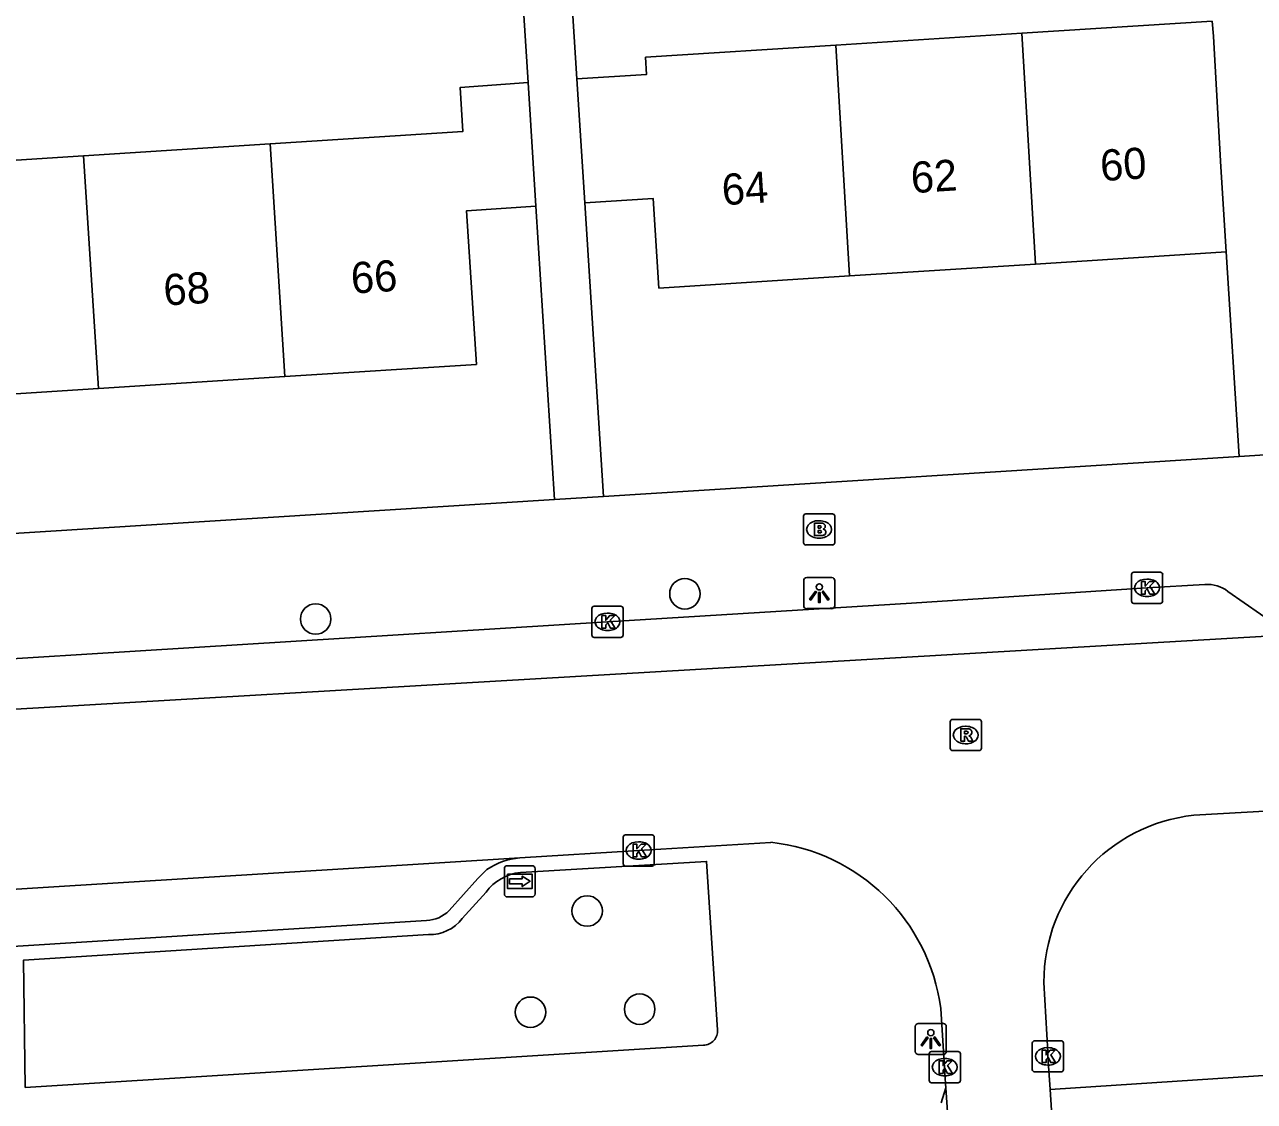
# Model space of a CAD drawing. Extents: x 159053 to 160041, y 380450 to 381422.
# Drawn here: x 159703.32 to 159742.79, y 381180.89 to 381215.45 of the extents above; entities that cross this region are included whole.
import ezdxf

# ---------------------------------------------------------------- set-up
doc = ezdxf.new("R2010")
doc.units = 0
for name, color, linetype in [('IMGEO_Boom', 7, 'Continuous'), ('IMGEO_Brandkraan', 7, 'Continuous'), ('IMGEO_Kolk', 7, 'Continuous'), ('IMGEO_Lichtpunt', 7, 'Continuous'), ('IMGEO_Pand', 7, 'Continuous'), ('IMGEO_Pand_nummerreeks', 7, 'Continuous'), ('IMGEO_Rijbaan_lokaal_open', 7, 'Continuous'), ('IMGEO_Rioolput', 7, 'Continuous'), ('IMGEO_Voetpad_open', 7, 'Continuous'), ('IMGEO_Wegwijzer', 7, 'Continuous')]:
    doc.layers.add(name, color=color, linetype=linetype)

msp = doc.modelspace()

# ---------------------------------------------------------------- linework, layer by layer
at = {"layer": 'IMGEO_Boom'}
for centre in [(159724.509, 381197.185), (159712.658, 381196.375), (159721.37, 381187.005), (159719.552, 381183.756), (159723.058, 381183.854)]:
    msp.add_circle(centre, 0.489, dxfattribs=at)
at = {"layer": 'IMGEO_Brandkraan'}
for p, q in [((159728.315, 381198.824), (159728.315, 381199.676)), ((159728.39, 381199.75), (159729.242, 381199.75)), ((159729.316, 381199.676), (159729.316, 381198.824)), ((159728.803, 381199.53), (159728.828, 381199.53)), ((159728.826, 381198.97), (159728.801, 381198.97)), ((159729.242, 381198.75), (159728.39, 381198.75))]:
    msp.add_line(p, q, dxfattribs=at)
for points in [[(159728.315, 381198.824), (159728.315, 381199.676)], [(159728.39, 381199.75), (159729.242, 381199.75)], [(159729.316, 381199.676), (159729.316, 381198.824)], [(159728.663, 381199.45), (159728.663, 381199.05), (159728.876, 381199.05)], [(159728.894, 381199.45), (159728.663, 381199.45)], [(159728.842, 381199.369), (159728.788, 381199.369), (159728.788, 381199.293)], [(159728.788, 381199.293), (159728.841, 381199.293)], [(159728.85, 381199.217), (159728.788, 381199.217), (159728.788, 381199.136)], [(159728.788, 381199.136), (159728.85, 381199.136)], [(159729.242, 381198.75), (159728.39, 381198.75)]]:
    msp.add_lwpolyline(points, dxfattribs=at)
for centre, radius, start, end in [((159728.392, 381199.674), 0.0765, 91.552, 178.448), ((159728.392, 381199.674), 0.0765, 91.552, 178.448), ((159729.24, 381199.674), 0.0765, 1.552, 88.448), ((159729.24, 381199.674), 0.0765, 1.552, 88.448), ((159728.843, 381199.331), 0.0379, 267.8285, 90.9355), ((159728.851, 381199.176), 0.0404, 269.8759, 90.5077), ((159728.898, 381199.305), 0.145, 59.4692, 91.5367), ((159728.923, 381199.352), 0.0922, 285.5137, 58.1501), ((159728.928, 381199.16), 0.105, 301.3115, 78.989), ((159728.392, 381198.826), 0.0765, 181.552, 268.448), ((159728.392, 381198.826), 0.0765, 181.552, 268.448), ((159728.882, 381199.301), 0.251, 268.6676, 293.5347), ((159729.24, 381198.826), 0.0765, 271.552, 358.448), ((159729.24, 381198.826), 0.0765, 271.552, 358.448)]:
    msp.add_arc(centre, radius, start, end, dxfattribs=at)
for centre, major_axis, ratio, start_param, end_param in [((159728.802, 381199.25), (-0.387, 0.002), 0.722429, 4.712389, 7.853982), ((159728.827, 381199.25), (-0.39, 0.002), 0.717154, 1.570796, 4.712389)]:
    msp.add_ellipse(centre, major_axis=major_axis, ratio=ratio, start_param=start_param, end_param=end_param, dxfattribs=at)
at = {"layer": 'IMGEO_Kolk'}
for p, q in [((159738.841, 381196.951), (159738.841, 381197.803)), ((159738.916, 381197.877), (159739.768, 381197.877)), ((159739.329, 381197.657), (159739.354, 381197.657)), ((159739.842, 381197.803), (159739.842, 381196.951)), ((159721.598, 381196.786), (159722.45, 381196.786)), ((159739.768, 381196.877), (159738.916, 381196.877)), ((159739.352, 381197.097), (159739.327, 381197.097)), ((159721.523, 381195.86), (159721.523, 381196.712)), ((159722.011, 381196.566), (159722.036, 381196.566)), ((159722.524, 381196.712), (159722.524, 381195.86)), ((159722.034, 381196.006), (159722.009, 381196.006)), ((159722.45, 381195.786), (159721.598, 381195.786)), ((159722.526, 381188.521), (159722.526, 381189.373)), ((159722.601, 381189.447), (159723.453, 381189.447)), ((159723.527, 381189.373), (159723.527, 381188.521)), ((159723.014, 381189.227), (159723.039, 381189.227)), ((159723.037, 381188.667), (159723.012, 381188.667)), ((159723.453, 381188.447), (159722.601, 381188.447)), ((159735.658, 381181.914), (159735.658, 381182.766)), ((159735.733, 381182.84), (159736.585, 381182.84)), ((159736.146, 381182.62), (159736.171, 381182.62)), ((159736.659, 381182.766), (159736.659, 381181.914)), ((159732.348, 381181.568), (159732.348, 381182.42)), ((159732.423, 381182.494), (159733.275, 381182.494)), ((159732.836, 381182.274), (159732.861, 381182.274)), ((159733.349, 381182.42), (159733.349, 381181.568)), ((159736.585, 381181.84), (159735.733, 381181.84)), ((159736.169, 381182.06), (159736.144, 381182.06)), ((159733.275, 381181.494), (159732.423, 381181.494)), ((159732.859, 381181.714), (159732.834, 381181.714))]:
    msp.add_line(p, q, dxfattribs=at)
for points in [[(159738.841, 381196.951), (159738.841, 381197.803)], [(159738.916, 381197.877), (159739.768, 381197.877)], [(159739.162, 381197.577), (159739.285, 381197.577), (159739.285, 381197.426), (159739.415, 381197.577), (159739.579, 381197.577), (159739.433, 381197.426), (159739.586, 381197.177), (159739.434, 381197.177), (159739.349, 381197.341), (159739.285, 381197.274), (159739.285, 381197.177), (159739.162, 381197.177), (159739.162, 381197.577)], [(159739.842, 381197.803), (159739.842, 381196.951)], [(159721.598, 381196.786), (159722.45, 381196.786)], [(159739.768, 381196.877), (159738.916, 381196.877)], [(159721.523, 381195.86), (159721.523, 381196.712)], [(159721.844, 381196.486), (159721.967, 381196.486), (159721.967, 381196.335), (159722.097, 381196.486), (159722.261, 381196.486), (159722.115, 381196.335), (159722.268, 381196.086), (159722.116, 381196.086), (159722.031, 381196.25), (159721.967, 381196.183), (159721.967, 381196.086), (159721.844, 381196.086), (159721.844, 381196.486)], [(159722.524, 381196.712), (159722.524, 381195.86)], [(159722.45, 381195.786), (159721.598, 381195.786)], [(159722.526, 381188.521), (159722.526, 381189.373)], [(159722.601, 381189.447), (159723.453, 381189.447)], [(159723.527, 381189.373), (159723.527, 381188.521)], [(159722.847, 381189.147), (159722.97, 381189.147), (159722.97, 381188.996), (159723.1, 381189.147), (159723.264, 381189.147), (159723.118, 381188.996), (159723.271, 381188.747), (159723.119, 381188.747), (159723.034, 381188.911), (159722.97, 381188.844), (159722.97, 381188.747), (159722.847, 381188.747), (159722.847, 381189.147)], [(159723.453, 381188.447), (159722.601, 381188.447)], [(159735.658, 381181.914), (159735.658, 381182.766)], [(159735.733, 381182.84), (159736.585, 381182.84)], [(159736.659, 381182.766), (159736.659, 381181.914)], [(159732.348, 381181.568), (159732.348, 381182.42)], [(159732.423, 381182.494), (159733.275, 381182.494)], [(159732.669, 381182.194), (159732.792, 381182.194), (159732.792, 381182.043), (159732.922, 381182.194), (159733.086, 381182.194), (159732.94, 381182.043), (159733.093, 381181.794), (159732.941, 381181.794), (159732.856, 381181.958), (159732.792, 381181.891), (159732.792, 381181.794), (159732.669, 381181.794), (159732.669, 381182.194)], [(159733.349, 381182.42), (159733.349, 381181.568)], [(159735.979, 381182.54), (159736.102, 381182.54), (159736.102, 381182.389), (159736.232, 381182.54), (159736.396, 381182.54), (159736.25, 381182.389), (159736.403, 381182.14), (159736.251, 381182.14), (159736.166, 381182.304), (159736.102, 381182.237), (159736.102, 381182.14), (159735.979, 381182.14), (159735.979, 381182.54)], [(159736.585, 381181.84), (159735.733, 381181.84)], [(159733.275, 381181.494), (159732.423, 381181.494)]]:
    msp.add_lwpolyline(points, dxfattribs=at)
for centre, start, end in [((159738.918, 381197.801), 91.552, 178.448), ((159738.918, 381197.801), 91.552, 178.448), ((159739.766, 381197.801), 1.552, 88.448), ((159739.766, 381197.801), 1.552, 88.448), ((159721.6, 381196.71), 91.552, 178.448), ((159721.6, 381196.71), 91.552, 178.448), ((159722.448, 381196.71), 1.552, 88.448), ((159722.448, 381196.71), 1.552, 88.448), ((159738.918, 381196.953), 181.552, 268.448), ((159738.918, 381196.953), 181.552, 268.448), ((159739.766, 381196.953), 271.552, 358.448), ((159739.766, 381196.953), 271.552, 358.448), ((159721.6, 381195.862), 181.552, 268.448), ((159721.6, 381195.862), 181.552, 268.448), ((159722.448, 381195.862), 271.552, 358.448), ((159722.448, 381195.862), 271.552, 358.448), ((159722.603, 381189.371), 91.552, 178.448), ((159722.603, 381189.371), 91.552, 178.448), ((159723.451, 381189.371), 1.552, 88.448), ((159723.451, 381189.371), 1.552, 88.448), ((159722.603, 381188.523), 181.552, 268.448), ((159722.603, 381188.523), 181.552, 268.448), ((159723.451, 381188.523), 271.552, 358.448), ((159723.451, 381188.523), 271.552, 358.448), ((159735.735, 381182.764), 91.552, 178.448), ((159735.735, 381182.764), 91.552, 178.448), ((159736.583, 381182.764), 1.552, 88.448), ((159736.583, 381182.764), 1.552, 88.448), ((159732.425, 381182.418), 91.552, 178.448), ((159732.425, 381182.418), 91.552, 178.448), ((159733.273, 381182.418), 1.552, 88.448), ((159733.273, 381182.418), 1.552, 88.448), ((159735.735, 381181.916), 181.552, 268.448), ((159735.735, 381181.916), 181.552, 268.448), ((159736.583, 381181.916), 271.552, 358.448), ((159736.583, 381181.916), 271.552, 358.448), ((159732.425, 381181.57), 181.552, 268.448), ((159732.425, 381181.57), 181.552, 268.448), ((159733.273, 381181.57), 271.552, 358.448), ((159733.273, 381181.57), 271.552, 358.448)]:
    msp.add_arc(centre, 0.0765, start, end, dxfattribs=at)
for centre, major_axis, ratio, start_param, end_param in [((159739.328, 381197.377), (-0.387, 0.002), 0.722429, 4.712389, 7.853982), ((159739.353, 381197.377), (-0.39, 0.002), 0.717154, 1.570796, 4.712389), ((159722.01, 381196.286), (-0.387, 0.002), 0.722429, 4.712389, 7.853982), ((159722.035, 381196.286), (-0.39, 0.002), 0.717154, 1.570796, 4.712389), ((159723.013, 381188.947), (-0.387, 0.002), 0.722429, 4.712389, 7.853982), ((159723.038, 381188.947), (-0.39, 0.002), 0.717154, 1.570796, 4.712389), ((159736.145, 381182.34), (-0.387, 0.002), 0.722429, 4.712389, 7.853982), ((159736.17, 381182.34), (-0.39, 0.002), 0.717154, 1.570796, 4.712389), ((159732.835, 381181.994), (-0.387, 0.002), 0.722429, 4.712389, 7.853982), ((159732.86, 381181.994), (-0.39, 0.002), 0.717154, 1.570796, 4.712389)]:
    msp.add_ellipse(centre, major_axis=major_axis, ratio=ratio, start_param=start_param, end_param=end_param, dxfattribs=at)
at = {"layer": 'IMGEO_Lichtpunt'}
for p, q in [((159728.323, 381197.608), (159728.323, 381196.801)), ((159728.323, 381197.608), (159728.323, 381196.801)), ((159729.225, 381197.703), (159728.417, 381197.703)), ((159729.225, 381197.703), (159728.417, 381197.703)), ((159729.319, 381196.801), (159729.319, 381197.608)), ((159729.319, 381196.801), (159729.319, 381197.608)), ((159728.417, 381196.707), (159729.225, 381196.707)), ((159728.417, 381196.707), (159729.225, 381196.707)), ((159732.804, 381183.396), (159731.996, 381183.396)), ((159732.804, 381183.396), (159731.996, 381183.396)), ((159731.902, 381183.301), (159731.902, 381182.494)), ((159731.902, 381183.301), (159731.902, 381182.494)), ((159732.898, 381182.494), (159732.898, 381183.301)), ((159732.898, 381182.494), (159732.898, 381183.301)), ((159731.996, 381182.4), (159732.804, 381182.4)), ((159731.996, 381182.4), (159732.804, 381182.4))]:
    msp.add_line(p, q, dxfattribs=at)
for points in [[(159728.697, 381197.272), (159728.736, 381197.244), (159728.548, 381196.982), (159728.51, 381197.009), (159728.697, 381197.272)], [(159728.799, 381197.224), (159728.846, 381197.224), (159728.846, 381196.902), (159728.799, 381196.902), (159728.799, 381197.224)], [(159728.909, 381197.244), (159728.947, 381197.271), (159729.134, 381197.009), (159729.095, 381196.981), (159728.909, 381197.244)], [(159732.276, 381182.965), (159732.315, 381182.937), (159732.127, 381182.675), (159732.089, 381182.702), (159732.276, 381182.965)], [(159732.488, 381182.937), (159732.526, 381182.964), (159732.713, 381182.702), (159732.674, 381182.674), (159732.488, 381182.937)], [(159732.378, 381182.917), (159732.425, 381182.917), (159732.425, 381182.595), (159732.378, 381182.595), (159732.378, 381182.917)]]:
    msp.add_lwpolyline(points, dxfattribs=at)
for centre in [(159728.822, 381197.406), (159732.401, 381183.099)]:
    msp.add_circle(centre, 0.0994, dxfattribs=at)
for centre, start, end in [((159728.417, 381197.608), 90, 180), ((159728.417, 381197.608), 90, 180), ((159729.225, 381197.608), 0, 90), ((159729.225, 381197.608), 0, 90), ((159728.417, 381196.801), 180, 270), ((159728.417, 381196.801), 180, 270), ((159729.225, 381196.801), 270, 0), ((159729.225, 381196.801), 270, 360), ((159731.996, 381183.301), 90, 180), ((159731.996, 381183.301), 90, 180), ((159732.804, 381183.301), 0, 90), ((159732.804, 381183.301), 0, 90), ((159731.996, 381182.494), 180, 270), ((159731.996, 381182.494), 180, 270), ((159732.804, 381182.494), 270, 0), ((159732.804, 381182.494), 270, 360)]:
    msp.add_arc(centre, 0.0946, start, end, dxfattribs=at)
at = {"layer": 'IMGEO_Pand'}
for points in [[(159735.32, 381215.173), (159741.434, 381215.563)], [(159741.884, 381208.156), (159741.705, 381210.889), (159741.481, 381214.879), (159741.47, 381215.076), (159741.434, 381215.563)], [(159729.351, 381214.792), (159735.32, 381215.173)], [(159735.765, 381207.766), (159735.32, 381215.173)], [(159721.044, 381213.709), (159723.281, 381213.851), (159723.246, 381214.403), (159729.351, 381214.792)], [(159729.351, 381214.792), (159729.796, 381207.385)], [(159711.2, 381211.62), (159717.381, 381212.014), (159717.291, 381213.431), (159719.476, 381213.588)], [(159719.729, 381209.619), (159719.476, 381213.588)], [(159721.044, 381213.709), (159721.299, 381209.732)], [(159705.21, 381211.238), (159711.2, 381211.62)], [(159711.2, 381211.62), (159711.674, 381204.153)], [(159699.22, 381210.857), (159705.21, 381211.238)], [(159705.21, 381211.238), (159705.684, 381203.771)], [(159729.796, 381207.385), (159723.673, 381206.995), (159723.49, 381209.872), (159721.299, 381209.732)], [(159719.729, 381209.619), (159717.502, 381209.476), (159717.816, 381204.544), (159711.674, 381204.153)], [(159741.884, 381208.156), (159735.765, 381207.766)], [(159735.765, 381207.766), (159729.796, 381207.385)], [(159711.674, 381204.153), (159705.684, 381203.771)], [(159705.684, 381203.771), (159699.694, 381203.389)]]:
    msp.add_lwpolyline(points, dxfattribs=at)
at = {"layer": 'IMGEO_Rijbaan_lokaal_open'}
for points in [[(159744.469, 381195.902), (159678.079, 381192.027), (159624.576, 381188.627), (159624.153, 381188.6)], [(159740.84, 381190.078), (159744.07, 381190.259), (159751.345, 381190.707), (159752.12, 381190.672), (159752.598, 381190.639), (159758.616, 381191.009), (159759.024, 381191.086), (159759.832, 381191.245), (159764.851, 381191.551)], [(159719.214, 381188.709), (159723.027, 381188.949), (159727.267, 381189.208)], [(159685.13, 381186.557), (159698.579, 381187.431), (159719.214, 381188.709)], [(159736.229, 381181.275), (159736.158, 381182.34), (159736.153, 381182.487), (159736.032, 381184.713)], [(159732.718, 381183.878), (159732.818, 381182.322), (159732.876, 381181.468), (159732.886, 381181.325)], [(159732.886, 381181.325), (159734.28, 381160.99)], [(159736.352, 381179.443), (159736.229, 381181.275)]]:
    msp.add_lwpolyline(points, dxfattribs=at)
for centre, radius, start, end in [((159741.411, 381184.729), 5.379, 96.0947, 180.1733), ((159726.608, 381183.082), 6.162, 7.4266, 83.8595)]:
    msp.add_arc(centre, radius, start, end, dxfattribs=at)
at = {"layer": 'IMGEO_Rioolput'}
for p, q in [((159733.022, 381192.226), (159733.022, 381193.078)), ((159733.097, 381193.152), (159733.949, 381193.152)), ((159733.51, 381192.932), (159733.535, 381192.932)), ((159734.023, 381193.078), (159734.023, 381192.226)), ((159733.949, 381192.152), (159733.097, 381192.152)), ((159733.533, 381192.372), (159733.508, 381192.372))]:
    msp.add_line(p, q, dxfattribs=at)
for points in [[(159733.022, 381192.226), (159733.022, 381193.078)], [(159733.097, 381193.152), (159733.949, 381193.152)], [(159733.611, 381192.85), (159733.359, 381192.852), (159733.359, 381192.452)], [(159734.023, 381193.078), (159734.023, 381192.226)], [(159733.359, 381192.452), (159733.483, 381192.452), (159733.483, 381192.614), (159733.494, 381192.614)], [(159733.537, 381192.771), (159733.483, 381192.771), (159733.483, 381192.69)], [(159733.483, 381192.69), (159733.535, 381192.69)], [(159733.541, 381192.585), (159733.612, 381192.452), (159733.752, 381192.452), (159733.687, 381192.578)], [(159733.949, 381192.152), (159733.097, 381192.152)]]:
    msp.add_lwpolyline(points, dxfattribs=at)
for centre, radius, start, end in [((159733.099, 381193.076), 0.0765, 91.552, 178.448), ((159733.099, 381193.076), 0.0765, 91.552, 178.448), ((159733.61, 381192.74), 0.109, 350.3612, 89.416), ((159733.947, 381193.076), 0.0765, 1.552, 88.448), ((159733.947, 381193.076), 0.0765, 1.552, 88.448), ((159733.493, 381192.561), 0.0533, 26.0293, 88.6989), ((159733.519, 381192.879), 0.19, 274.7715, 282.9687), ((159733.543, 381192.675), 0.0964, 77.0061, 93.1865), ((159733.557, 381192.732), 0.0378, 276.6634, 79.6772), ((159733.608, 381192.74), 0.112, 277.5842, 350.9817), ((159733.592, 381192.525), 0.108, 29.5134, 73.7905), ((159733.099, 381192.228), 0.0765, 181.552, 268.448), ((159733.099, 381192.228), 0.0765, 181.552, 268.448), ((159733.947, 381192.228), 0.0765, 271.552, 358.448), ((159733.947, 381192.228), 0.0765, 271.552, 358.448)]:
    msp.add_arc(centre, radius, start, end, dxfattribs=at)
for centre, major_axis, ratio, start_param, end_param in [((159733.509, 381192.652), (-0.387, 0.002), 0.722429, 4.712389, 7.853982), ((159733.534, 381192.652), (-0.39, 0.002), 0.717154, 1.570796, 4.712389)]:
    msp.add_ellipse(centre, major_axis=major_axis, ratio=ratio, start_param=start_param, end_param=end_param, dxfattribs=at)
at = {"layer": 'IMGEO_Voetpad_open'}
for points in [[(159730.476, 381227.5), (159720.21, 381226.855), (159721.044, 381213.709)], [(159719.476, 381213.588), (159718.637, 381226.753), (159708.65, 381226.125)], [(159720.32, 381200.208), (159719.729, 381209.619)], [(159721.299, 381209.732), (159721.891, 381200.306)], [(159742.296, 381201.587), (159741.884, 381208.156)], [(159742.296, 381201.587), (159721.891, 381200.306)], [(159744.3, 381201.713), (159742.296, 381201.587)], [(159720.32, 381200.208), (159668.917, 381196.982), (159655.668, 381196.153)], [(159721.891, 381200.306), (159720.32, 381200.208)], [(159605.214, 381188.99), (159624.483, 381190.151), (159627.059, 381190.306), (159630.83, 381190.546), (159640.79, 381191.163), (159677.748, 381193.503), (159698.589, 381194.827), (159722.024, 381196.285), (159731.777, 381196.886), (159739.342, 381197.376), (159741.195, 381197.48)], [(159741.935, 381197.26), (159743.503, 381196.162)], [(159719.227, 381188.239), (159725.207, 381188.598), (159725.559, 381183.193)], [(159718.156, 381188.334), (159717.861, 381188.045), (159716.94, 381187.02)], [(159717.364, 381186.759), (159718.127, 381187.612)], [(159716.22, 381186.702), (159698.659, 381185.596), (159688.376, 381184.957)], [(159703.34, 381181.336), (159703.279, 381185.426), (159716.281, 381186.246)], [(159725.101, 381182.699), (159703.34, 381181.336)], [(159736.229, 381181.275), (159743.572, 381181.753)], [(159732.733, 381180.848), (159732.886, 381181.325)]]:
    msp.add_lwpolyline(points, dxfattribs=at)
for centre, radius, start, end in [((159741.289, 381196.441), 1.043, 51.7266, 95.1592), ((159719.355, 381186.63), 2.083, 93.8885, 125.1444), ((159719.39, 381186.675), 1.573, 95.9494, 143.4169), ((159716.187, 381187.751), 1.05, 271.8129, 315.846), ((159716.312, 381187.581), 1.335, 268.6756, 322.0168), ((159725.095, 381183.164), 0.465, 270.7662, 3.565)]:
    msp.add_arc(centre, radius, start, end, dxfattribs=at)
at = {"layer": 'IMGEO_Wegwijzer'}
for p, q in [((159718.714, 381187.557), (159718.714, 381188.357)), ((159718.714, 381188.357), (159718.714, 381187.557)), ((159718.814, 381188.457), (159719.604, 381188.457)), ((159719.604, 381188.457), (159718.814, 381188.457)), ((159719.704, 381188.357), (159719.704, 381187.557)), ((159719.704, 381187.557), (159719.704, 381188.357)), ((159719.604, 381187.457), (159718.814, 381187.457)), ((159718.814, 381187.457), (159719.604, 381187.457))]:
    msp.add_line(p, q, dxfattribs=at)
for points in [[(159718.815, 381188.189), (159719.603, 381188.189), (159719.603, 381187.725), (159718.815, 381187.725), (159718.815, 381188.189)], [(159718.88, 381188.041), (159718.88, 381187.957), (159718.88, 381187.873), (159719.291, 381187.873), (159719.291, 381187.79), (159719.538, 381187.957), (159719.291, 381188.124), (159719.291, 381188.041), (159718.88, 381188.041)]]:
    msp.add_lwpolyline(points, dxfattribs=at)
for centre, start, end in [((159718.814, 381188.357), 90, 180), ((159718.814, 381188.357), 90, 180), ((159719.604, 381188.357), 0, 90), ((159719.604, 381188.357), 360, 90), ((159718.814, 381187.557), 180, 270), ((159718.814, 381187.557), 180, 270), ((159719.604, 381187.557), 270, 0), ((159719.604, 381187.557), 270, 0)]:
    msp.add_arc(centre, 0.1, start, end, dxfattribs=at)

# ---------------------------------------------------------------- texts
at = {"layer": 'IMGEO_Pand_nummerreeks'}
for s, rotation, p in [('60', 3.6478, (159737.866, 381210.425)), ('62', 3.6478, (159731.79, 381210.038)), ('64', 3.6478, (159725.723, 381209.651)), ('66', 3.6469, (159713.82, 381206.814)), ('68', 3.6469, (159707.803, 381206.431))]:
    msp.add_text(s, height=1, rotation=rotation, dxfattribs=at).set_placement(p)

doc.saveas('drawing.dxf')
